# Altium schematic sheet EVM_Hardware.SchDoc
size 431 x 279 mm; Date: Not shown in title block; ApprovedBy: Not shown in title block; CheckedBy: Not shown in title block; Author: Not shown in title block; CompanyName: Not shown in title block; Engineer: Not shown in title block; Organization: Not shown in title block; Address1: Not shown in title block; Address2: Not shown in title block; Address3: Not shown in title block; Address4: Not shown in title block; DocumentNumber: 35; Revision: Use project parameter SCH_Rev; SheetNumber: 35; SheetTotal: 35; PageSetup: Record=PageOptions¦CenterHorizontal=True¦CenterVertical=True¦PrintScale=1.00¦XCorrection=1.00¦YCorrection=1.00¦PrintKind=0¦BorderSize=5000000¦LeftOffset=0¦BottomOffset=0¦Orientation=2¦PaperLength=1000¦PaperWidth=1000¦Scale=100¦PaperSource=15¦PrintQuality=600¦MediaType=1¦DitherType=10¦PaperKind=Letter¦PrintScaleMode=1
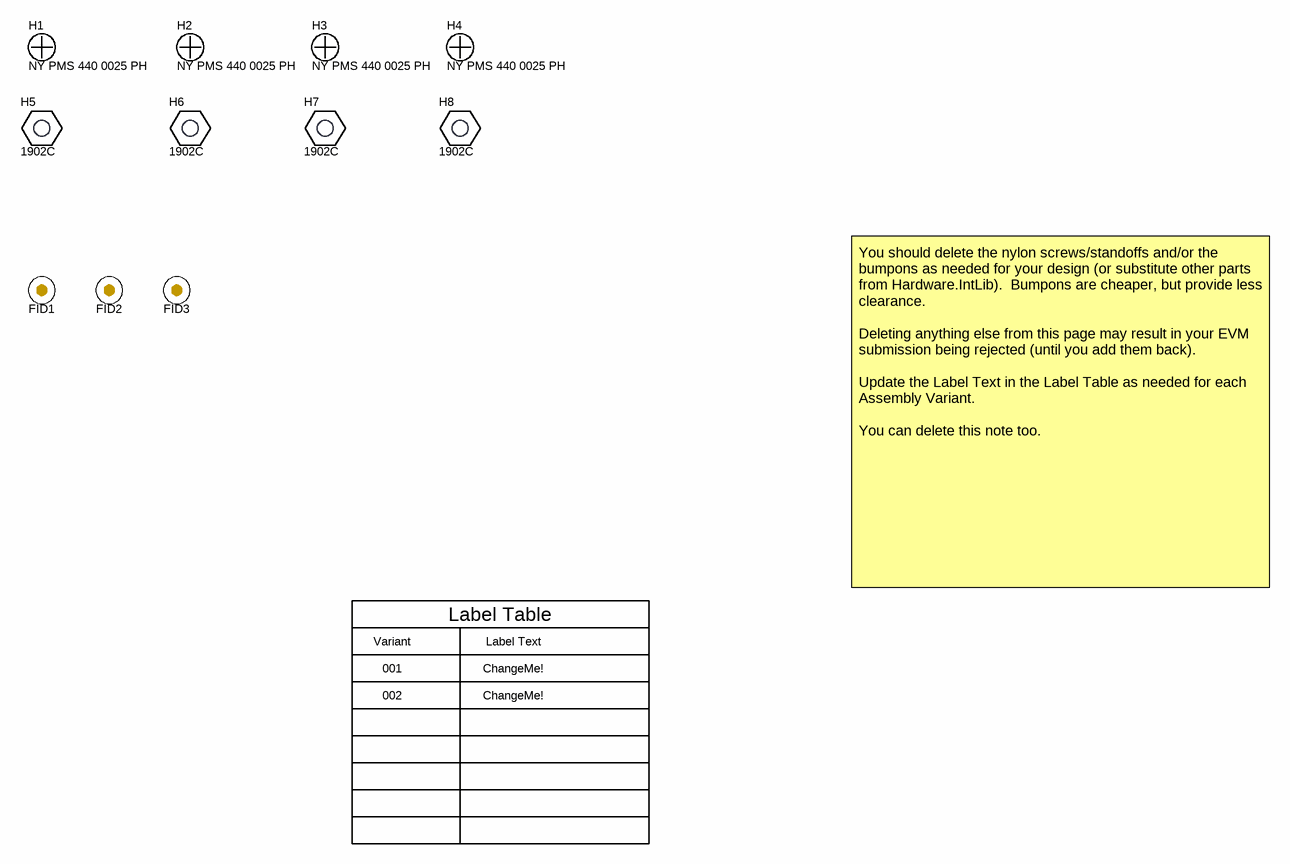
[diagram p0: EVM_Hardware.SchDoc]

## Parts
FID1  Fiducial  [Fiducial10-20]  (value not drawn)
FID2  Fiducial  [Fiducial10-20]  (value not drawn)
FID3  Fiducial  [Fiducial10-20]  (value not drawn)
H1  NY PMS 440 0025 PH  [NY PMS 440 0025 PH]
H2  NY PMS 440 0025 PH  [NY PMS 440 0025 PH]
H3  NY PMS 440 0025 PH  [NY PMS 440 0025 PH]
H4  NY PMS 440 0025 PH  [NY PMS 440 0025 PH]
H5  1902C  [Keystone_1902C]
H6  1902C  [Keystone_1902C]
H7  1902C  [Keystone_1902C]
H8  1902C  [Keystone_1902C]

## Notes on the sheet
- Variant
- Label Table
- Label Text
- You should delete the nylon screws/standoffs and/or the bumpons as needed for your design (or substitute other parts from Hardware.IntLib).  Bumpons are cheaper, but provide less clearance.
  Deleting anything else from this page may result in your EVM submission being rejected (until you add them back).
  Update the Label Text in the Label Table as needed for each Assembly Variant.
  You can delete this note too.
- 001
- 002
- ChangeMe!

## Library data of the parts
FID1-FID3 = Fiducial: Fiducial mark.  There is nothing to buy or mount.; SymbolCreator: codlsc
H1-H4 = NY PMS 440 0025 PH: Machine Screw, Round, #4-40 x 1/4, Nylon, Philips panhead; Manufacturer: B&F Fastener Supply; CompType: Hardware; SymbolCreator: codlsc; U/M: EA
H5-H8 = 1902C: Standoff, Hex, 0.5"L #4-40 Nylon; Manufacturer: Keystone; CompType: Hardware; SymbolCreator: a0412235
